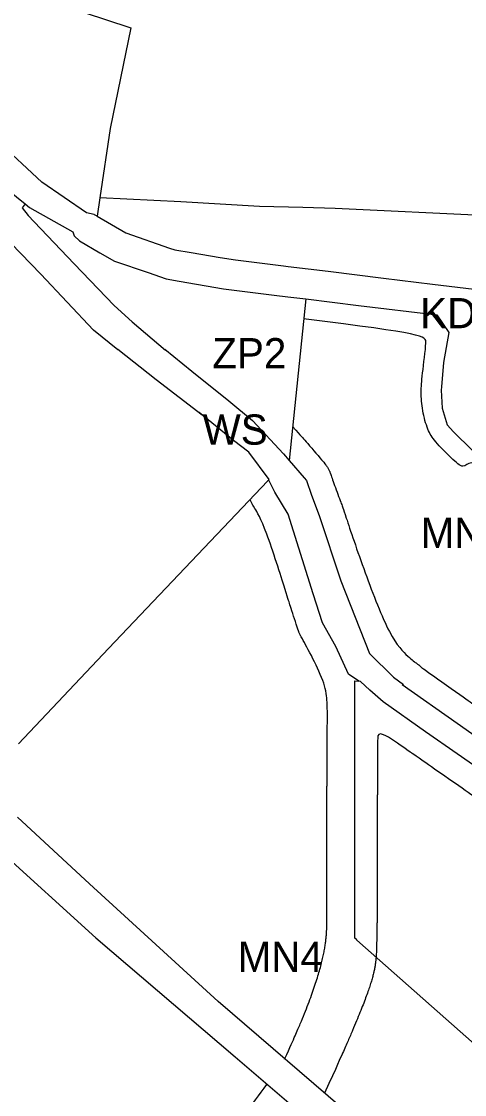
# Model space of a CAD drawing. Extents: x 7413438 to 7416393, y 5541665 to 5544118.
# Drawn here: x 7414186.3 to 7414274.3, y 5542859.3 to 5543072.4 of the extents above; entities that cross this region are included whole.
import ezdxf

# ---------------------------------------------------------------- set-up
doc = ezdxf.new("R2010")
doc.units = 0
for name, color, linetype in [('linie_rozgraniczajace', 7, 'Continuous'), ('linie_zabudowy_nieprzekraczalne', 7, 'Continuous'), ('oznaczenia_przeznaczen', 7, 'Continuous')]:
    doc.layers.add(name, color=color, linetype=linetype)

msp = doc.modelspace()

# ---------------------------------------------------------------- linework, layer by layer
at = {"layer": 'linie_rozgraniczajace'}
for p, q in [((7414157.31, 5543088.01), (7414207.82, 5543071.23)), ((7414208.01, 5543071.16), (7414203.92, 5543051.22)), ((7414207.82, 5543071.23), (7414208.01, 5543071.16)), ((7414190.36, 5543040.51), (7414171.66, 5543057.97)), ((7414163.36, 5543055.1), (7414187.05, 5543036.24)), ((7414203.92, 5543051.22), (7414201.91, 5543037.43)), ((7414199.23, 5543034.46), (7414190.36, 5543040.51)), ((7414201.91, 5543037.43), (7414201.36, 5543033.76)), ((7414217.98, 5543036.61), (7414201.91, 5543037.43)), ((7414233.59, 5543035.7), (7414217.98, 5543036.61)), ((7414187.05, 5543036.24), (7414186.43, 5543035.46)), ((7414186.43, 5543035.46), (7414187.68, 5543033.91)), ((7414187.05, 5543036.24), (7414187.94, 5543035.5)), ((7414187.94, 5543035.5), (7414196.53, 5543030.69)), ((7414200.72, 5543034.13), (7414199.23, 5543034.46)), ((7414242.17, 5543035.48), (7414233.59, 5543035.7)), ((7414248.57, 5543035.32), (7414242.17, 5543035.48)), ((7414295.95, 5543033.02), (7414248.57, 5543035.32)), ((7414187.68, 5543033.91), (7414188.81, 5543032.63)), ((7414188.81, 5543032.63), (7414196.77, 5543024.33)), ((7414200.83, 5543034.06), (7414200.72, 5543034.13)), ((7414201.36, 5543033.76), (7414200.83, 5543034.06)), ((7414201.36, 5543033.76), (7414207.05, 5543030.45)), ((7414190.14, 5543022.24), (7414182.22, 5543030.49)), ((7414196.53, 5543030.69), (7414196.79, 5543029.87)), ((7414207.05, 5543030.45), (7414215.73, 5543027.44)), ((7414196.79, 5543029.87), (7414197.81, 5543028.88)), ((7414197.81, 5543028.88), (7414201.87, 5543026.52)), ((7414201.87, 5543026.52), (7414204.81, 5543024.87)), ((7414215.73, 5543027.44), (7414216.75, 5543027.09)), ((7414216.75, 5543027.09), (7414220, 5543026.54)), ((7414220, 5543026.54), (7414225.77, 5543025.56)), ((7414196.77, 5543024.33), (7414204.74, 5543016.03)), ((7414204.81, 5543024.87), (7414211.48, 5543022.56)), ((7414225.77, 5543025.56), (7414228.82, 5543025.11)), ((7414228.82, 5543025.11), (7414238.37, 5543023.92)), ((7414238.37, 5543023.92), (7414239.28, 5543023.81)), ((7414239.28, 5543023.81), (7414247.2, 5543022.82)), ((7414200.63, 5543011.13), (7414190.14, 5543022.24)), ((7414211.48, 5543022.56), (7414215.02, 5543021.34)), ((7414247.2, 5543022.82), (7414258.2, 5543021.48)), ((7414215.02, 5543021.34), (7414217.63, 5543020.89)), ((7414217.63, 5543020.89), (7414226.4, 5543019.37)), ((7414258.2, 5543021.48), (7414267.9, 5543020.3)), ((7414267.9, 5543020.3), (7414277.85, 5543019.08)), ((7414226.4, 5543019.37), (7414236.48, 5543018.11)), ((7414236.48, 5543018.11), (7414239.22, 5543017.77)), ((7414239.22, 5543017.77), (7414242.74, 5543017.33)), ((7414204.74, 5543016.03), (7414208.27, 5543012.77)), ((7414242.74, 5543017.33), (7414239.48, 5542985.27)), ((7414242.74, 5543017.33), (7414253.25, 5543016.04)), ((7414253.25, 5543016.04), (7414268.77, 5543014.15)), ((7414268.77, 5543014.15), (7414271.18, 5543010.67)), ((7414205.42, 5543007.26), (7414200.63, 5543011.13)), ((7414208.27, 5543012.77), (7414214.89, 5543007.15)), ((7414271.18, 5543010.67), (7414270.12, 5543004.74)), ((7414205.44, 5543007.27), (7414205.42, 5543007.26)), ((7414213.05, 5543001.27), (7414205.44, 5543007.27)), ((7414214.9, 5543007.15), (7414214.81, 5543007.36)), ((7414214.81, 5543007.36), (7414220.11, 5543002.97)), ((7414214.89, 5543007.15), (7414214.9, 5543007.15)), ((7414270.12, 5543004.74), (7414269.71, 5542999.9)), ((7414220.11, 5543002.97), (7414227.48, 5542997.13)), ((7414222.16, 5542994.23), (7414213.05, 5543001.27)), ((7414269.71, 5542999.9), (7414269.65, 5542999.22)), ((7414269.65, 5542999.22), (7414269.86, 5542995.62)), ((7414227.48, 5542997.13), (7414232.2, 5542993.18)), ((7414228.38, 5542989.21), (7414221.6, 5542994.78)), ((7414221.6, 5542994.78), (7414222.16, 5542994.23)), ((7414269.86, 5542995.62), (7414270.86, 5542992.35)), ((7414232.2, 5542993.18), (7414238.36, 5542986.59)), ((7414270.86, 5542992.35), (7414272.07, 5542990.97)), ((7414272.07, 5542990.97), (7414275.78, 5542987.28)), ((7414231.46, 5542986.93), (7414228.38, 5542989.21)), ((7414235.51, 5542981.46), (7414231.46, 5542986.93)), ((7414238.36, 5542986.59), (7414239.48, 5542985.27)), ((7414239.48, 5542985.27), (7414242.47, 5542981.79)), ((7414235.24, 5542981.18), (7414203.63, 5542947.88)), ((7414235.42, 5542981.36), (7414235.24, 5542981.18)), ((7414235.42, 5542981.36), (7414235.51, 5542981.46)), ((7414236.6, 5542978.97), (7414235.42, 5542981.36)), ((7414242.47, 5542981.79), (7414242.89, 5542981.3)), ((7414242.89, 5542981.3), (7414243.92, 5542978.35)), ((7414239.26, 5542974.6), (7414236.6, 5542978.97)), ((7414243.92, 5542978.35), (7414245.41, 5542974.35)), ((7414244.21, 5542958.79), (7414239.26, 5542974.6)), ((7414245.41, 5542974.35), (7414249.75, 5542961.34)), ((7414249.75, 5542961.34), (7414255.39, 5542946.89)), ((7414246.11, 5542952.98), (7414244.21, 5542958.79)), ((7414248.7, 5542948.28), (7414246.11, 5542952.98)), ((7414203.63, 5542947.88), (7414185.7, 5542928.99)), ((7414251.25, 5542942.83), (7414248.7, 5542948.28)), ((7414255.39, 5542946.89), (7414260.15, 5542942.19)), ((7414253.31, 5542941.41), (7414251.25, 5542942.83)), ((7414252.49, 5542890.38), (7414252.53, 5542941.11)), ((7414252.53, 5542941.11), (7414252.53, 5542941.47)), ((7414252.53, 5542941.47), (7414253.31, 5542941.41)), ((7414253.65, 5542941.38), (7414253.31, 5542941.41)), ((7414255.48, 5542939.64), (7414253.65, 5542941.38)), ((7414260.15, 5542942.19), (7414262.14, 5542940.74)), ((7414262.14, 5542940.74), (7414261.92, 5542940.75)), ((7414261.92, 5542940.75), (7414272.83, 5542933.05)), ((7414258.15, 5542937.34), (7414255.48, 5542939.64)), ((7414266.51, 5542931.38), (7414258.15, 5542937.34)), ((7414272.83, 5542933.05), (7414285.64, 5542923.95)), ((7414281.45, 5542920.96), (7414266.51, 5542931.38)), ((7414199.85, 5542901.18), (7414185.53, 5542914.43)), ((7414180.96, 5542908.72), (7414201.08, 5542890.47)), ((7414225.35, 5542877.76), (7414199.85, 5542901.18)), ((7414201.08, 5542890.47), (7414228.73, 5542866.78)), ((7414252.49, 5542890.37), (7414252.49, 5542890.38)), ((7414252.87, 5542890.03), (7414252.49, 5542890.37)), ((7414252.89, 5542889.96), (7414252.87, 5542890.03)), ((7414266.01, 5542878.36), (7414252.89, 5542889.96)), ((7414255.9, 5542851.55), (7414225.35, 5542877.76)), ((7414284.74, 5542861.79), (7414266.01, 5542878.36)), ((7414228.73, 5542866.78), (7414246.56, 5542851.56))]:
    msp.add_line(p, q, dxfattribs=at)
at = {"layer": 'linie_zabudowy_nieprzekraczalne'}
for points, degree in [([(7414289.31, 5542972.21), (7414277.42, 5542981.08), (7414278.75, 5542983.47), (7414275.17, 5542985.42), (7414274.19, 5542983.43), (7414271.84, 5542985.48), (7414268.18, 5542989.26), (7414266.98, 5542991.14), (7414265.83, 5542995.18), (7414265.61, 5542998.97), (7414265.8, 5543001.77), (7414266.89, 5543009.73), (7414266.45, 5543010.38), (7414242.28, 5543013.37)], 3), ([(7414240.16, 5542991.91), (7414241.96, 5542989.98), (7414242.1, 5542989.82), (7414246.63, 5542984.53), (7414246.67, 5542984.48), (7414246.87, 5542984.22), (7414247.05, 5542983.95), (7414247.22, 5542983.67), (7414247.37, 5542983.38), (7414247.5, 5542983.08), (7414247.55, 5542982.93), (7414248.56, 5542980.04), (7414250.04, 5542976.08), (7414250.09, 5542975.92), (7414254.4, 5542963.03), (7414259.61, 5542949.68), (7414263.34, 5542945.99), (7414265.03, 5542944.76), (7414265.22, 5542944.61), (7414265.47, 5542944.4), (7414265.7, 5542944.17), (7414265.75, 5542944.11), (7414275.66, 5542937.11), (7414275.67, 5542937.1), (7414288.45, 5542928.02), (7414300.93, 5542919.38), (7414300.97, 5542919.36), (7414301.01, 5542919.33), (7414318.78, 5542906.52), (7414342.51, 5542890.98), (7414348.64, 5542887.02), (7414349.3, 5542894.98), (7414350.7, 5542909.29), (7414351.82, 5542916.53), (7414354.71, 5542928.72), (7414357.45, 5542937.52), (7414359.24, 5542941.89), (7414358.67, 5542943.69), (7414356.12, 5542945.09), (7414354.88, 5542945.44)], 3), ([(7414238.57, 5542866.36), (7414239.71, 5542868.86), (7414240.75, 5542871.2), (7414241.68, 5542873.39), (7414242.51, 5542875.42), (7414243.25, 5542877.31), (7414243.9, 5542879.06), (7414244.47, 5542880.68), (7414244.97, 5542882.18), (7414245.39, 5542883.57), (7414245.75, 5542884.85), (7414246.05, 5542886.04), (7414246.29, 5542887.13), (7414246.49, 5542888.14), (7414246.64, 5542889.08), (7414246.75, 5542889.95), (7414246.83, 5542890.76), (7414246.89, 5542891.52), (7414246.92, 5542892.23), (7414246.94, 5542892.9), (7414246.95, 5542893.55), (7414246.95, 5542894.17), (7414246.96, 5542894.78), (7414246.96, 5542895.37), (7414246.96, 5542895.95), (7414246.96, 5542896.51), (7414246.96, 5542897.06), (7414246.96, 5542897.59), (7414246.96, 5542898.12), (7414246.96, 5542898.63), (7414246.96, 5542899.13), (7414246.95, 5542899.63), (7414246.95, 5542900.11), (7414246.95, 5542900.59), (7414246.95, 5542901.05), (7414246.95, 5542901.51), (7414246.94, 5542901.97), (7414246.94, 5542902.41), (7414246.94, 5542902.86), (7414246.94, 5542903.29), (7414246.93, 5542903.73), (7414246.93, 5542904.16), (7414246.93, 5542904.59), (7414246.93, 5542905.01), (7414246.93, 5542905.44), (7414246.92, 5542905.87), (7414246.92, 5542906.29), (7414246.92, 5542906.73), (7414246.92, 5542907.16), (7414246.92, 5542907.6), (7414246.92, 5542908.05), (7414246.92, 5542908.5), (7414246.92, 5542908.97), (7414246.92, 5542909.44), (7414246.92, 5542909.92), (7414246.93, 5542910.42), (7414246.93, 5542910.93), (7414246.93, 5542911.45), (7414246.93, 5542911.99), (7414246.93, 5542912.54), (7414246.93, 5542913.12), (7414246.94, 5542913.71), (7414246.94, 5542914.32), (7414246.94, 5542914.95), (7414246.95, 5542915.61), (7414246.95, 5542916.29), (7414246.95, 5542917.01), (7414246.96, 5542917.76), (7414246.96, 5542918.54), (7414246.97, 5542919.37), (7414246.97, 5542920.24), (7414246.98, 5542921.16), (7414246.98, 5542922.13), (7414246.99, 5542923.16), (7414246.99, 5542924.24), (7414247, 5542925.39), (7414247.01, 5542926.6), (7414247.01, 5542927.88), (7414247.02, 5542929.24), (7414247.03, 5542930.67), (7414247.04, 5542932.17), (7414247.04, 5542933.76), (7414247.06, 5542937.21), (7414246.66, 5542940.7), (7414244.19, 5542946), (7414241.67, 5542950.55), (7414241.66, 5542950.57), (7414241.51, 5542950.87), (7414241.39, 5542951.17), (7414241.3, 5542951.42), (7414239.4, 5542957.23), (7414239.39, 5542957.28), (7414234.62, 5542972.5), (7414232.27, 5542976.35), (7414232.15, 5542976.56), (7414232.06, 5542976.74), (7414231.71, 5542977.45)], 3), ([(7414345.63, 5542871.9), (7414341.8, 5542873.9), (7414341.8, 5542873.9), (7414341.66, 5542873.98), (7414336.75, 5542876.75), (7414330.81, 5542880.08), (7414330.65, 5542880.17), (7414330.38, 5542880.35), (7414330.35, 5542880.37), (7414324.63, 5542884.45), (7414324.51, 5542884.54), (7414314.11, 5542892.45), (7414314.07, 5542892.48), (7414307.65, 5542897.47), (7414299.58, 5542902.65), (7414299.49, 5542902.71), (7414278.6, 5542916.79), (7414278.53, 5542916.84), (7414263.6, 5542927.26), (7414263.58, 5542927.28), (7414263.56, 5542927.29), (7414257.17, 5542931.84), (7414257.03, 5542930.07), (7414257.02, 5542929.27), (7414257.02, 5542928.48), (7414257.02, 5542927.68), (7414257.01, 5542926.88), (7414257.01, 5542926.08), (7414257, 5542925.28), (7414257, 5542924.49), (7414256.99, 5542923.69), (7414256.99, 5542922.91), (7414256.98, 5542922.12), (7414256.98, 5542921.35), (7414256.98, 5542920.58), (7414256.97, 5542919.83), (7414256.97, 5542919.08), (7414256.96, 5542918.35), (7414256.96, 5542917.63), (7414256.95, 5542916.93), (7414256.95, 5542916.24), (7414256.95, 5542915.57), (7414256.94, 5542914.92), (7414256.94, 5542914.29), (7414256.94, 5542913.68), (7414256.93, 5542913.09), (7414256.93, 5542912.52), (7414256.93, 5542911.96), (7414256.93, 5542911.41), (7414256.93, 5542910.88), (7414256.93, 5542910.35), (7414256.92, 5542909.82), (7414256.92, 5542909.31), (7414256.92, 5542908.79), (7414256.92, 5542908.27), (7414256.92, 5542907.75), (7414256.92, 5542907.22), (7414256.92, 5542906.69), (7414256.92, 5542906.15), (7414256.92, 5542905.6), (7414256.92, 5542905.03), (7414256.92, 5542904.45), (7414256.92, 5542903.85), (7414256.92, 5542903.23), (7414256.92, 5542902.59), (7414256.92, 5542901.93), (7414256.93, 5542901.24), (7414256.93, 5542900.54), (7414256.93, 5542899.83), (7414256.93, 5542899.1), (7414256.93, 5542898.36), (7414256.92, 5542897.61), (7414256.92, 5542896.86), (7414256.92, 5542896.1), (7414256.92, 5542895.35), (7414256.91, 5542894.59), (7414256.9, 5542893.83), (7414256.9, 5542893.08), (7414256.89, 5542892.34), (7414256.88, 5542891.61), (7414256.86, 5542890.89), (7414256.85, 5542890.19), (7414256.83, 5542889.5), (7414256.81, 5542888.83), (7414256.79, 5542888.18), (7414256.77, 5542887.55), (7414256.74, 5542886.94), (7414256.69, 5542886.33), (7414256.63, 5542885.7), (7414256.54, 5542885.05), (7414256.42, 5542884.35), (7414256.26, 5542883.6), (7414256.05, 5542882.78), (7414255.8, 5542881.88), (7414255.49, 5542880.88), (7414255.11, 5542879.77), (7414254.66, 5542878.53), (7414254.14, 5542877.16), (7414253.54, 5542875.64), (7414252.85, 5542873.95), (7414252.06, 5542872.08), (7414251.17, 5542870.02), (7414250.18, 5542867.75), (7414249.07, 5542865.25), (7414246.49, 5542859.56)], 3), ([(7414199.06, 5542812.85), (7414235.06, 5542861.31)], 1)]:
    msp.add_open_spline(points, degree=degree, dxfattribs=at)

# ---------------------------------------------------------------- texts
at = {"layer": 'oznaczenia_przeznaczen'}
for s, p in [('KDW', (7414265.47, 5543011.52)), ('ZP2', (7414224.19, 5543003.56)), ('WS', (7414222.28, 5542988.39)), ('MN1', (7414265.55, 5542967.86)), ('MN4', (7414229.22, 5542883.67))]:
    msp.add_text(s, height=6, dxfattribs=at).set_placement(p)

doc.saveas('drawing.dxf')
